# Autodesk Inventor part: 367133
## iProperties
Created: 2006-08
Part Number: 367133
Material: 10.9 vz
Description: Senkschraube
Vendor: Autodesk Inc.
Document SubType Name: Modeling
Standard: DIN 7991
Designer: I.Baliuc
Standards Organization: DIN
Language: de-DE
Size Designation: M10 x 25
Categories: <MemberInstance Version="R10.0.0"><Categories><Category DisplayName="Schrauben" InternalName="e4da775c-781d-43d5-af7c-5136215cf5a6" Mnemonic="FSTN"><Category Di
Density: 7.85 g/cm^3
Mass: 19.0818 g
Surface Area: 14.5184 cm^2
Volume: 2.4308 cm^3
Abmessung: M10 x 25
Author: T.Messerschmitt
Comments: DIN 7991 - M10 x 25
Revision Number: 367133
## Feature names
1. Körper [Revolution]
2. Loch [Extrusion]
3. Fase1 [Chamfer]
